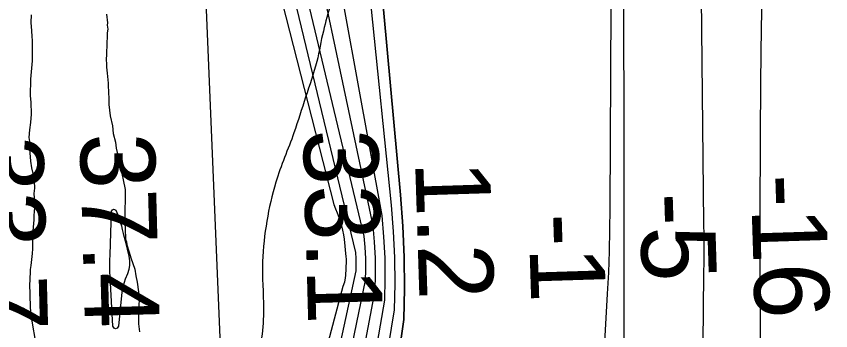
# Model space of a CAD drawing. Extents: x 3313447 to 3351316, y 703786 to 729172.
# Drawn here: x 3322283 to 3323012, y 726058 to 726340 of the extents above; entities that cross this region are included whole.
import ezdxf

# ---------------------------------------------------------------- set-up
doc = ezdxf.new("R2010")
doc.units = 0
for name, color, linetype in [('V-GRID-MAJR', 7, 'Continuous'), ('V-RIVR-EDGE', 7, 'Continuous'), ('V-RIVR-RANG', 7, 'Continuous'), ('V-RRAP-FSHR', 7, 'Continuous'), ('V-SITE-VEGE', 7, 'Continuous'), ('V-TOPO-DPTH', 7, 'Continuous'), ('V-TOPO-MAJR', 7, 'Continuous'), ('V-TOPO-MINR', 7, 'Continuous'), ('V-TOPO-WATR', 7, 'Continuous')]:
    doc.layers.add(name, color=color, linetype=linetype)

msp = doc.modelspace()

# ---------------------------------------------------------------- linework, layer by layer
at = {"layer": 'V-GRID-MAJR'}
msp.add_spline([(3322840.097, 715233.372), (3322833.044, 721295.0380000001), (3322825.991, 727356.734), (3322825.989, 727358.642)], degree=3, dxfattribs=at)
at = {"layer": 'V-RIVR-EDGE'}
msp.add_spline([(3322621.39367418, 727358.3440878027), (3322620.017507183, 727344.96628995), (3322617.494746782, 727330.465586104), (3322616.640161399, 727320.1055978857), (3322620.7439808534, 727303.5160881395), (3322619.4605654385, 727287.3543835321), (3322619.8156031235, 727263.3134304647), (3322623.0412646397, 727226.8308575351), (3322631.523999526, 727137.2813263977), (3322631.0326509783, 727106.1962372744), (3322631.78167231, 727073.8646289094), (3322633.7710635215, 727040.2865013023), (3322632.837561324, 726998.0114360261), (3322629.425369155, 726959.0583722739), (3322631.0146273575, 726931.2840108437), (3322631.385038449, 726913.4602805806), (3322630.5058556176, 726893.1527358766), (3322630.0257809, 726866.6269434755), (3322631.585317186, 726826.832617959), (3322632.7324217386, 726787.8682803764), (3322631.8306912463, 726758.4421422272), (3322628.8381050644, 726721.5604611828), (3322624.2439619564, 726707.4793633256), (3322616.3124439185, 726684.7023526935), (3322612.969944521, 726673.9340323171), (3322610.4502588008, 726660.6767730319), (3322609.184266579, 726651.5612542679), (3322610.3508441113, 726620.4720655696), (3322608.515611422, 726548.7708621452), (3322601.30954216, 726484.1291681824), (3322595.0103278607, 726450.9860199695), (3322590.8245169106, 726434.4170080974), (3322587.496366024, 726429.4514290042), (3322580.435831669, 726423.666110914), (3322577.5242120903, 726419.5284699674), (3322577.102556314, 726416.62812422), (3322577.0892326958, 726411.2398644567), (3322579.968055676, 726402.1140967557), (3322579.100146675, 726386.3658487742), (3322569.100320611, 726365.2518886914), (3322564.5051526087, 726350.756309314), (3322557.812979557, 726326.3182979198), (3322551.9425952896, 726298.9768660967), (3322541.9161219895, 726267.0863864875), (3322531.475167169, 726235.1969317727), (3322515.200724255, 726190.8873799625), (3322507.239484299, 726156.0904052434), (3322503.4199848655, 726120.0397370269), (3322504.1444087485, 726077.7605721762), (3322502.421914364, 726051.6523359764), (3322495.2886125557, 726016.43882995), (3322494.4360769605, 726006.9078047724), (3322495.1943223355, 725978.3065300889), (3322498.8201168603, 725936.0201909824), (3322500.818732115, 725906.1723970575), (3322498.3205691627, 725901.6192496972), (3322497.879440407, 725890.843755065), (3322497.4096146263, 725868.4627778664), (3322499.048067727, 725860.5835294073), (3322502.748679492, 725848.5543412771), (3322506.036859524, 725837.3551410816), (3322506.012262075, 725827.4075845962), (3322505.579332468, 725819.9479421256), (3322505.98049037, 725814.5586574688), (3322509.2748197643, 725805.8463463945), (3322509.26252104, 725800.8725681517), (3322508.4140850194, 725792.999469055), (3322508.8060188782, 725783.8798507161), (3322512.0900993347, 725771.0227244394), (3322513.7193283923, 725759.413142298), (3322513.2659009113, 725743.6638694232), (3322513.6322124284, 725724.1822130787), (3322513.5748183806, 725700.971247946), (3322513.546121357, 725689.3657653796), (3322510.2128460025, 725682.3277786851), (3322506.053682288, 725676.5352863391), (3322504.79691411, 725671.1501012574), (3322504.7641175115, 725657.88669261), (3322502.246481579, 725645.4583963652), (3322500.142302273, 725632.6145937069), (3322495.5512338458, 725619.7769404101), (3322492.6426889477, 725616.8827440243), (3322491.8045018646, 725613.1544601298), (3322492.567871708, 725586.6255930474), (3322492.145191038, 725583.3107657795), (3322488.8190899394, 725579.1741497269), (3322487.15603939, 725577.1058417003), (3322487.5428487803, 725565.9138157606), (3322492.0529506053, 725546.0074289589), (3322493.291270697, 725543.9319466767), (3322498.677480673, 725543.0896600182), (3322504.468948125, 725538.5160147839), (3322506.1084261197, 725531.0512478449), (3322507.7233066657, 725513.6389244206), (3322508.084493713, 725492.0848604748), (3322504.3408364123, 725486.7058247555), (3322500.588979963, 725478.0109368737), (3322499.2973653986, 725458.5333801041), (3322498.03239807, 725449.83234286), (3322493.4597777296, 725444.4553569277), (3322492.2112087, 725442.3860240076), (3322491.7885280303, 725439.0711967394), (3322497.5830701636, 725435.7409960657), (3322499.2327970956, 725432.421044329), (3322501.673566, 725413.7632265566), (3322499.976693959, 725398.0170283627), (3322496.643418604, 725390.9790416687), (3322495.809331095, 725388.9086838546), (3322496.2156134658, 725385.5918067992), (3322498.682004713, 725377.2960270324), (3322502.389790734, 725368.1682095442), (3322503.179807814, 725352.4158619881), (3322500.5924791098, 725311.8028223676), (3322499.2957400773, 725290.2528579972), (3322496.8016767, 725287.3576367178), (3322495.555157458, 725286.1172668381), (3322495.126327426, 725280.3155504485), (3322495.113003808, 725274.9272906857), (3322499.2424456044, 725268.6998189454), (3322500.0560352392, 725262.4805463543), (3322500.852201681, 725249.21508792), (3322500.418247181, 725241.3409639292), (3322499.165578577, 725237.6137049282), (3322496.6684405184, 725233.475039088), (3322496.24063538, 725228.0878042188), (3322496.218087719, 725218.9692107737), (3322496.2088636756, 725215.2388770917), (3322492.455982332, 725206.12950769), (3322492.847916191, 725197.0098893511), (3322495.686768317, 725171.7193423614), (3322501.0135344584, 725146.8371275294), (3322500.974588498, 725131.0868297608), (3322500.922318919, 725109.9482722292), (3322499.2541439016, 725105.8075566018), (3322497.175586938, 725103.325791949), (3322497.168412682, 725100.4244213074), (3322499.1947000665, 725081.7676284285), (3322501.214838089, 725060.6239464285), (3322504.05778979, 725036.9913255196), (3322501.9700087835, 725030.7792271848), (3322500.710165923, 725024.1505975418), (3322501.1041495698, 725015.8599422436), (3322506.0359071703, 724998.8539011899), (3322509.70167255, 724972.7323413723), (3322511.7084869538, 724946.2003996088), (3322509.619681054, 724939.573819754), (3322507.546248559, 724939.1644627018), (3322507.120493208, 724934.6061908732), (3322506.6885884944, 724927.561029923), (3322506.6783395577, 724923.4162147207), (3322510.801631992, 724914.701853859), (3322512.017404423, 724903.5077781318), (3322512.409338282, 724894.3881597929), (3322511.1546198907, 724889.8319377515), (3322507.404813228, 724881.9660129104), (3322507.3966140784, 724878.6501607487), (3322507.798796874, 724873.6753576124), (3322511.099275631, 724867.4499356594), (3322513.565666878, 724859.1541558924), (3322513.1399115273, 724854.5958840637), (3322510.643798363, 724850.8716997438), (3322513.5349200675, 724846.7197102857), (3322517.228357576, 724831.7891515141), (3322520.1266535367, 724830.5385326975), (3322525.070709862, 724818.5062698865), (3322527.088798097, 724796.533624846), (3322526.2598350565, 724796.5356746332), (3322525.8422788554, 724795.2932549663), (3322517.139191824, 724795.729259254), (3322516.7144613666, 724791.5854689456), (3322517.1248433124, 724789.9265179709), (3322525.409349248, 724787.8336124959), (3322527.474582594, 724784.9271173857), (3322529.4895961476, 724761.7110277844), (3322532.3274233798, 724736.0059992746), (3322531.0511822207, 724722.7456653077), (3322528.140587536, 724719.0225058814), (3322527.714832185, 724714.4642340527), (3322529.773916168, 724709.0708498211), (3322531.8422241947, 724707.4077992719), (3322531.8350499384, 724704.5064286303), (3322529.70524829, 724681.3005879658), (3322528.0309239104, 724674.672983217), (3322523.0366477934, 724666.395651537), (3322520.542584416, 724663.5004302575), (3322520.523111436, 724655.6252813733), (3322520.0686590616, 724639.4615269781)], degree=3, dxfattribs=at)
at = {"layer": 'V-RRAP-FSHR'}
msp.add_lwpolyline([(3322431.258565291, 727358.0675405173), (3322429.6418011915, 726904.7021123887), (3322510.566473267, 724962.8540465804), (3322576.3154653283, 723396.5395491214), (3322621.0663133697, 721565.6439314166)], dxfattribs=at)
at = {"layer": 'V-SITE-VEGE'}
for points in [[(3322296.219, 726070.175), (3322295.4790000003, 726079.26), (3322294.853, 726100.311), (3322295.285, 726102.371), (3322295.381, 726112.687), (3322296.2430000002, 726116.394), (3322297.171, 726127.115), (3322297.622, 726131.236), (3322297.773, 726147.329), (3322298.693, 726157.225), (3322298.727, 726160.9400000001), (3322299.178, 726165.063), (3322299.643, 726170.834), (3322299.252, 726172.903), (3322298.914, 726180.746), (3322299.373, 726185.694), (3322299.389, 726187.345), (3322298.248, 726197.6730000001), (3322296.657, 726203.879), (3322295.8850000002, 726209.662), (3322294.752, 726220.816), (3322294.816, 726227.4180000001), (3322294.437, 726231.135), (3322294.912, 726237.734), (3322295.801, 726244.329), (3322296.282, 726251.753), (3322295.973, 726262.484), (3322295.612, 726268.2660000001), (3322295.754, 726283.122), (3322297.148, 726299.6140000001), (3322297.187, 726303.741), (3322297.316, 726317.772), (3322296.9420000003, 726321.4890000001), (3322296.575, 726326.4450000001), (3322296.233, 726333.875), (3322296.299, 726340.892)], [(3322363.571, 726341.4940000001), (3322364.323, 726333.648), (3322364.304, 726331.584), (3322364.681, 726327.8640000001), (3322364.237, 726324.567), (3322364.21, 726321.68), (3322363.735, 726315.081), (3322363.645, 726305.59), (3322363.186, 726300.642), (3322363.563, 726296.9230000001), (3322363.536, 726294.036), (3322364.311, 726288.664), (3322365.0500000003, 726279.579), (3322365.031, 726277.514), (3322365.742, 726265.54), (3322365.6950000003, 726260.59), (3322366.838, 726250.262), (3322368.818, 726241.576), (3322369.576, 726234.551), (3322371.5670000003, 726226.693), (3322372.341, 726221.321), (3322373.131, 726217.6), (3322374.727, 726211.806), (3322376.316, 726205.189), (3322377.094, 726200.231), (3322380.2460000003, 726184.519), (3322379.986, 726156.8690000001), (3322380.301, 726146.551), (3322380.678, 726142.834), (3322380.6520000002, 726139.944), (3322381.454, 726137.462), (3322381.844, 726134.984), (3322383.844, 726128.361), (3322385.448, 726123.392), (3322389.065, 726113.042), (3322389.835, 726107.256), (3322391.019, 726101.468), (3322392.174, 726092.791), (3322392.954, 726087.831), (3322392.929, 726085.355), (3322392.4790000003, 726081.232), (3322392.843, 726076.278), (3322392.389, 726071.742), (3322392.3170000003, 726064.314), (3322393.071, 726056.879)], [(3322300.13, 726047.4400000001), (3322297.009, 726066.452), (3322296.219, 726070.175)]]:
    msp.add_lwpolyline(points, dxfattribs=at)
at = {"layer": 'V-TOPO-DPTH'}
for points in [[(3322446.291441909, 727060.2165192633), (3322610.1736339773, 726161.0959380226), (3322611.769506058, 726142.198720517), (3322612.8079542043, 726123.2832341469), (3322613.010266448, 726104.34034448), (3322612.6551547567, 726085.3791859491), (3322488.6743743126, 725370.4509089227), (3322487.8078002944, 725349.5118847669), (3322487.239951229, 725328.567957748), (3322487.120189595, 725307.6166764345), (3322487.2991529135, 725286.6604922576), (3322496.824701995, 724791.5408622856), (3322497.65556152, 724747.7092945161), (3322498.4698789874, 724703.877424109), (3322499.259383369, 724660.0450997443)], [(3322549.8561720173, 724561.8557197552), (3322528.801114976, 725184.9950225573), (3322528.0144552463, 725209.1203078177), (3322527.2657592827, 725233.2467263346), (3322526.5740089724, 725257.3748447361), (3322525.920222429, 725281.5040963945), (3322524.7662803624, 725326.0333540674), (3322524.739607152, 725327.8985499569), (3322524.7872572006, 725331.6276512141), (3322524.861580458, 725333.491556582), (3322525.158066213, 725339.2476320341), (3322525.4576978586, 725342.1352699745), (3322629.8986936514, 726067.9340090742), (3322630.48452255, 726095.8799987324), (3322630.331320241, 726123.807257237), (3322629.069571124, 726151.7064190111), (3322627.0687908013, 726179.5868496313), (3322552.420344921, 726993.0845297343)], [(3322549.8561720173, 724561.8557197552), (3322528.801114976, 725184.9950225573), (3322528.0144552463, 725209.1203078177), (3322527.2657592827, 725233.2467263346), (3322526.5740089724, 725257.3748447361), (3322525.920222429, 725281.5040963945), (3322524.7662803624, 725326.0333540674), (3322524.739607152, 725327.8985499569), (3322524.7872572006, 725331.6276512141), (3322524.861580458, 725333.491556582), (3322525.158066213, 725339.2476320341), (3322525.4576978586, 725342.1352699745), (3322629.8986936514, 726067.9340090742), (3322630.48452255, 726095.8799987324), (3322630.331320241, 726123.807257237), (3322629.069571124, 726151.7064190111), (3322627.0687908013, 726179.5868496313), (3322552.420344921, 726993.0845297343)], [(3322887.874169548, 726903.8513096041), (3322889.89827548, 726824.9599733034), (3322891.6393698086, 726746.0631531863), (3322892.9559467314, 726667.1581073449), (3322893.9895120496, 726588.2475776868), (3322898.5060803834, 726154.2689115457), (3322898.5879260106, 726142.9488853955), (3322898.62182155, 726131.6288680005), (3322898.5837919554, 726120.308863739), (3322898.497812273, 726108.9888682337), (3322897.152049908, 725984.0641979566), (3322895.6312455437, 725910.3135355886), (3322893.1433391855, 725836.6050509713), (3322889.2047798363, 725762.9598329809), (3322884.299118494, 725689.3567927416), (3322859.960541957, 725371.3991511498), (3322858.665003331, 725356.6933436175), (3322857.145237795, 725342.0133522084), (3322855.289131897, 725327.3720849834), (3322853.2087990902, 725312.7566338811), (3322846.1585168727, 725266.9941860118), (3322843.2267887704, 725248.8230170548), (3322602.521419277, 724601.5518235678)], [(3322887.874169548, 726903.8513096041), (3322889.89827548, 726824.9599733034), (3322891.6393698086, 726746.0631531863), (3322892.9559467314, 726667.1581073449), (3322893.9895120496, 726588.2475776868), (3322898.5060803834, 726154.2689115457), (3322898.5879260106, 726142.9488853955), (3322898.62182155, 726131.6288680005), (3322898.5837919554, 726120.308863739), (3322898.497812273, 726108.9888682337), (3322897.152049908, 725984.0641979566), (3322895.6312455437, 725910.3135355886), (3322893.1433391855, 725836.6050509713), (3322889.2047798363, 725762.9598329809), (3322884.299118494, 725689.3567927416), (3322859.960541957, 725371.3991511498), (3322858.665003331, 725356.6933436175), (3322857.145237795, 725342.0133522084), (3322855.289131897, 725327.3720849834), (3322853.2087990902, 725312.7566338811), (3322846.1585168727, 725266.9941860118), (3322843.2267887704, 725248.8230170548), (3322602.521419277, 724601.5518235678)]]:
    msp.add_lwpolyline(points, dxfattribs=at)
at = {"layer": 'V-TOPO-MAJR'}
msp.add_lwpolyline([(3322385.913870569, 726960.0035415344), (3322586.535264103, 726128.0091619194), (3322586.836178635, 726122.5280891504), (3322586.894817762, 726117.0390756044), (3322586.7919399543, 726111.5447682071), (3322427.323724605, 725375.2936773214), (3322426.9061696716, 725367.2064972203), (3322426.6041915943, 725359.1162422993), (3322426.4755788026, 725351.0213751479), (3322426.462542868, 725342.9234331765), (3322426.532346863, 725334.8231531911), (3322426.596904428, 725326.7228339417), (3322426.6535923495, 725318.6224557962), (3322426.7050338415, 725310.5220383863), (3322426.898974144, 725277.4529261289), (3322427.0652611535, 725252.8181154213), (3322427.260628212, 725228.1835610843), (3322427.4996153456, 725203.5493913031), (3322427.7676825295, 725178.9154778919), (3322434.455812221, 724610.5595691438)], dxfattribs=at)
at = {"layer": 'V-TOPO-MINR'}
for points in [[(3322392.1409231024, 727358.0106447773), (3322393.996268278, 727284.5016237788), (3322399.858928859, 727081.7961704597), (3322400.8413484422, 727057.3236929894), (3322402.1888085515, 727032.8754405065), (3322404.08382945, 727008.4635255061), (3322406.3438908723, 726984.0758354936), (3322416.4352316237, 726887.0334621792), (3322594.1070643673, 726142.6893276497), (3322594.947337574, 726132.7393853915), (3322595.494114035, 726122.7798239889), (3322595.6006453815, 726112.8058338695), (3322595.413679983, 726102.8222246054), (3322451.9483891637, 725408.1433398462), (3322450.1576227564, 725367.7493655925), (3322448.912173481, 725327.3441046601), (3322448.4846999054, 725286.9219137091), (3322448.6025434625, 725246.4884360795), (3322448.80435065, 725231.0082071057), (3322449.428163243, 725182.8260870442), (3322450.046228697, 725134.6438937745), (3322450.6556734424, 725086.4615906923), (3322451.259371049, 725038.2792144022), (3322456.8528678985, 724588.6395593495)], [(3322454.22347942, 727358.1009424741), (3322448.30788716, 727187.6791849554), (3322447.68851915, 727167.8117505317), (3322447.1627460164, 727147.9421703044), (3322446.7773651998, 727128.0693713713), (3322446.485579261, 727108.1944266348), (3322446.225846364, 727084.8955905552), (3322446.178582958, 727076.6687592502), (3322446.190572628, 727068.4423344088), (3322446.291441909, 727060.2165192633), (3322610.1736339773, 726161.0959380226), (3322611.769506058, 726142.198720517), (3322612.8079542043, 726123.2832341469), (3322613.010266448, 726104.34034448), (3322612.6551547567, 726085.3791859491), (3322488.6743743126, 725370.4509089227), (3322487.8078002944, 725349.5118847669), (3322487.239951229, 725328.567957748), (3322487.120189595, 725307.6166764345), (3322487.2991529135, 725286.6604922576), (3322496.824701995, 724791.5408622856), (3322497.65556152, 724747.7092945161), (3322498.4698789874, 724703.877424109), (3322499.259383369, 724660.0450997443)], [(3322546.840045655, 727358.2356512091), (3322515.456786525, 727073.3401223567), (3322516.2489117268, 727056.5457564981), (3322517.4603237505, 727039.7896380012), (3322519.3006660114, 727023.0908905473), (3322521.5602950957, 727006.4303904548), (3322537.039506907, 726906.4562144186), (3322546.821604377, 726839.7693579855), (3322555.893941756, 726772.9918243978), (3322563.9016389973, 726706.0782750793), (3322618.4799955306, 726170.328661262), (3322620.3382779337, 726146.945242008), (3322621.53425012, 726123.5420468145), (3322621.7367569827, 726100.1091877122), (3322621.2769536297, 726076.656552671), (3322508.689833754, 725388.5029068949), (3322506.807013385, 725351.9183461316), (3322506.347942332, 725340.5443325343), (3322506.0569430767, 725329.1678824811), (3322506.018051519, 725317.7877777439), (3322506.1472317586, 725306.4052365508), (3322518.44068928, 724758.3799058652), (3322519.338764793, 724720.1154977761), (3322520.289765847, 724681.8524600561)], [(3322355.31900018, 726999.65040548), (3322567.1733859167, 726170.9518101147), (3322568.789616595, 726167.22052394), (3322570.3176619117, 726163.455229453), (3322571.7134291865, 726159.6389224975), (3322573.0210111, 726155.7886072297), (3322574.140121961, 726151.8869192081), (3322575.097772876, 726147.9511342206), (3322575.8132338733, 726143.964203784), (3322576.367234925, 726139.9431763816), (3322578.038667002, 726124.2805610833), (3322578.17826511, 726122.2763558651), (3322578.1890072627, 726121.2723173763), (3322578.170220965, 726120.2673109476), (3322577.6508240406, 726107.5365803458), (3322577.471090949, 726105.4897989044), (3322576.675044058, 726101.4829726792), (3322575.26041383, 726097.630221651), (3322383.095388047, 725372.3147367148)], [(3322807.5962466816, 727000.1238501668), (3322811.8264245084, 726787.5630805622), (3322813.6123214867, 726677.8407741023), (3322814.868112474, 726568.1143216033), (3322815.3287444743, 726458.3816500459), (3322815.2592704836, 726348.6448324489), (3322814.487582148, 726167.3459817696), (3322814.258875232, 726148.2599053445), (3322813.8336778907, 726129.1797266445), (3322813.1137449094, 726110.1083945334), (3322812.1973215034, 726091.0429601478), (3322805.575524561, 725972.4027021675)], [(3322971.9709649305, 726929.7677684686), (3322972.020286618, 726884.1456031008), (3322970.8156695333, 726838.5393173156), (3322968.7750932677, 726792.9436179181), (3322967.539225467, 726771.8316043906), (3322964.446864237, 726715.6787270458), (3322961.613428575, 726659.5136845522), (3322959.168381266, 726603.3303943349), (3322956.982259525, 726547.1349389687), (3322952.762426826, 726428.066109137), (3322951.2603855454, 726378.9181294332), (3322950.077759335, 726329.7640220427), (3322949.374255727, 726280.6007231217), (3322948.990167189, 726231.4312965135), (3322948.7816619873, 726160.463508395), (3322948.757890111, 726146.7733966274), (3322948.756051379, 726133.0833082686), (3322948.787112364, 726119.3932550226), (3322948.840106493, 726105.7032251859), (3322949.8695109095, 725902.7696821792)], [(3322887.874169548, 726903.8513096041), (3322889.89827548, 726824.9599733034), (3322891.6393698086, 726746.0631531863), (3322892.9559467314, 726667.1581073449), (3322893.9895120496, 726588.2475776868), (3322898.5060803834, 726154.2689115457), (3322898.5879260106, 726142.9488853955), (3322898.62182155, 726131.6288680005), (3322898.5837919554, 726120.308863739), (3322898.497812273, 726108.9888682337), (3322897.152049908, 725984.0641979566), (3322895.6312455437, 725910.3135355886), (3322893.1433391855, 725836.6050509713), (3322889.2047798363, 725762.9598329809), (3322884.299118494, 725689.3567927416), (3322859.960541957, 725371.3991511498), (3322858.665003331, 725356.6933436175), (3322857.145237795, 725342.0133522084), (3322855.289131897, 725327.3720849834), (3322853.2087990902, 725312.7566338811), (3322846.1585168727, 725266.9941860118), (3322843.2267887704, 725248.8230170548), (3322602.521419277, 724601.5518235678)], [(3322443.0617683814, 726894.1580011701), (3322452.3264059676, 726860.204803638), (3322602.139488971, 726151.891560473), (3322603.3574894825, 726137.4685020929), (3322604.150063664, 726123.0315006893), (3322604.3044983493, 726108.5735847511), (3322604.0335067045, 726094.1017257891), (3322470.4055060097, 725389.1686675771), (3322469.0988011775, 725358.5686904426), (3322468.2164311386, 725327.9608940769), (3322467.970563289, 725297.3413688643), (3322468.149030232, 725266.7140244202), (3322470.488588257, 725122.5230649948), (3322472.074881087, 725023.4856322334), (3322473.6336734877, 724924.4477723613), (3322475.1512152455, 724825.4092718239), (3322476.6412565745, 724726.3703441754), (3322479.006972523, 724566.92010775)], [(3322369.6991344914, 726166.9041513), (3322370.6921362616, 726166.6539107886), (3322371.7990353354, 726165.8298310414), (3322373.6044597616, 726161.6673097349), (3322374.8484332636, 726158.4453253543), (3322375.92327585, 726155.1630446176), (3322376.885364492, 726151.84056631), (3322377.7521917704, 726148.4852009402), (3322378.605466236, 726145.1264361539), (3322379.4384114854, 726141.7625722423), (3322380.2578039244, 726138.3953089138), (3322383.5488104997, 726124.6907766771), (3322384.112918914, 726120.70420578), (3322384.184484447, 726116.7550478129), (3322383.5172356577, 726112.8620092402), (3322382.3574439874, 726109.0063835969), (3322380.377866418, 726104.1533651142), (3322379.331092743, 726101.3245707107), (3322378.472506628, 726098.4330930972), (3322377.824562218, 726095.4893294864), (3322377.4085945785, 726092.5039405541), (3322374.365590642, 726061.9720429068), (3322373.042522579, 726060.3353007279), (3322371.741367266, 726059.6507344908), (3322370.473081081, 726060.3944321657), (3322369.226707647, 726062.0903057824), (3322366.8766407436, 726106.1234931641), (3322366.6783195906, 726111.1119422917), (3322366.570357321, 726116.1011192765), (3322366.597933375, 726121.0913880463), (3322366.71586831, 726126.0823846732), (3322368.1687201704, 726165.109275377), (3322368.8769786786, 726166.2936329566), (3322369.6991344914, 726166.9041513)]]:
    msp.add_lwpolyline(points, dxfattribs=at)
at = {"layer": 'V-TOPO-WATR'}
msp.add_lwpolyline([(3322552.420344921, 726993.0845297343), (3322627.0687908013, 726179.5868496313), (3322629.069571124, 726151.7064190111), (3322630.331320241, 726123.807257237), (3322630.48452255, 726095.8799987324), (3322629.8986936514, 726067.9340090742), (3322525.4576978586, 725342.1352699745), (3322525.158066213, 725339.2476320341), (3322524.861580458, 725333.491556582), (3322524.7872572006, 725331.6276512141), (3322524.739607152, 725327.8985499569), (3322524.7662803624, 725326.0333540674), (3322525.920222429, 725281.5040963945), (3322526.5740089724, 725257.3748447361), (3322527.2657592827, 725233.2467263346), (3322528.0144552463, 725209.1203078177), (3322528.801114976, 725184.9950225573), (3322549.8561720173, 724561.8557197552)], dxfattribs=at)

# ---------------------------------------------------------------- texts
at = {"layer": 'V-RIVR-RANG'}
for s, height, rotation, p in [('33.1', 66.99999999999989, 271.5283257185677, (3322539.6513481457, 726237.6149061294)), ('33.7', 66.99999999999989, 271.5283257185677, (3322239.715030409, 726231.2440773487)), ('37.4', 66.99999999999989, 271.5283257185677, (3322339.673030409, 726234.1590773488)), ('1.2', 66.99999999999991, 271.81175, (3322640.0137217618, 726209.4997159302)), ('-16', 67.00000000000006, 271.81175, (3322940.545548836, 726197.4145505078)), ('-5', 67.00000000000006, 271.81175, (3322841.021207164, 726180.7908720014)), ('-1', 67.00000000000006, 271.81175, (3322741.556242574, 726162.3206598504))]:
    msp.add_text(s, height=height, rotation=rotation, dxfattribs=at).set_placement(p)

doc.saveas('drawing.dxf')
